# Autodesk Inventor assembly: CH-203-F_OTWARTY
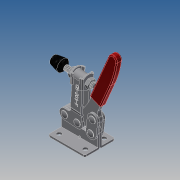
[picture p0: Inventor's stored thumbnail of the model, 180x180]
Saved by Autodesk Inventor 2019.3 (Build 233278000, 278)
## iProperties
Company: Î¢ÈíÖÐ¹ú
Created: 2011-05
Part Number: CH-203-F_OTWARTY
Material: Ogólny
Description: STEP AP203
Document SubType Name: Assembly
Designer: CADENGINEERING4
Sending System: SolidWorks 2010
Preprocessor: SwSTEP 2.0
Title: CH-203-F.STEP
Author: Î¢ÈíÓÃ»§
Revision Number: ÈÎºÎ
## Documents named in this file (10)
- E:\STRONA\Horizontal toggle clamp\CH-203-F\CH-203-F_OTWARTY.iam
- E:\STRONA\Horizontal toggle clamp\CH-203-F\225-D-06.ipt
- E:\STRONA\Horizontal toggle clamp\CH-203-F\203-F-02.ipt
- E:\STRONA\Horizontal toggle clamp\CH-203-F\203-F-04.ipt
- E:\STRONA\Horizontal toggle clamp\CH-203-F\56212-02.ipt
- E:\STRONA\Horizontal toggle clamp\CH-203-F\203-F-03.ipt
- E:\STRONA\Horizontal toggle clamp\CH-203-F\FW516.ipt
- E:\STRONA\Horizontal toggle clamp\CH-203-F\203-F-01.ipt
- E:\STRONA\Horizontal toggle clamp\CH-203-F\203-F-03-02.ipt
- E:\STRONA\Horizontal toggle clamp\CH-203-F\56212.ipt
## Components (15 placed, 15 different names)
1. 225-D-06_1 — Zestawiające:18, Zestawiające:19
2. 225-D-06_2 — Zestawiające:26, Zestawiające:28, Zestawiające:29
3. 203-F-02_3 — Równoległe:1, Zestawiające:5, Zestawiające:7, Zestawiające:9, Zestawiające:25, Zestawiające:26, Zestawiające:27, Zestawiające:29, Zestawiające:30
4. 225-D-06_4 — Zestawiające:20, Zestawiające:22, Zestawiające:23
5. 225-D-06_5 — Zestawiające:13, Zestawiające:30
6. 203-F-04_6 — Zestawiające:14, Zestawiające:16, Zestawiające:18, Zestawiające:19, Zestawiające:21, Zestawiające:22, Zestawiające:23, Zestawiające:24
7. 56212-02_7 — Równoległe:3, Zestawiające:4, Zestawiające:8
8. 203-F-03_8 — Zestawiające:10, Zestawiające:11, Zestawiające:12, Zestawiające:13, Zestawiające:20, Zestawiające:24, Zestawiające:27, Przejściowe:1
9. FW516_9 — Równoległe:2, Zestawiające:1, Zestawiające:5, Zestawiające:6
10. 56212-02_10 — Zestawiające:3, Zestawiające:6
11. 203-F-01_11 — Zestawiające:14, Zestawiające:15, Zestawiające:16, Zestawiające:17, Zestawiające:25, Zestawiające:28, Przejściowe:1
12. 203-F-03-02_12 — Zestawiające:10, Zestawiające:11, Zestawiające:12
13. FW516_13 — Równoległe:1, Równoległe:2, Zestawiające:2, Zestawiające:7, Zestawiające:8
14. 203-F-04_14 — Zestawiające:15, Zestawiające:17, Zestawiające:21
15. 56212_15 — Równoległe:3, Zestawiające:1, Zestawiające:2, Zestawiające:3, Zestawiające:4, Zestawiające:9
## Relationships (34: Mate 30, Flush 3, Transitional 1)
- Równoległe:1 [Flush]: 203-F-02_3 ↔ FW516_13
- Równoległe:2 [Flush]: FW516_9 ↔ FW516_13
- Równoległe:3 [Flush]: 56212-02_7 ↔ 56212_15
- Zestawiające:1 [Mate]: FW516_9 ↔ 56212_15
- Zestawiające:2 [Mate]: FW516_13 ↔ 56212_15
- Zestawiające:3 [Mate]: 56212-02_10 ↔ 56212_15
- Zestawiające:4 [Mate]: 56212-02_7 ↔ 56212_15
- Zestawiające:5 [Mate]: 203-F-02_3 ↔ FW516_9
- Zestawiające:6 [Mate]: FW516_9 ↔ 56212-02_10
- Zestawiające:7 [Mate]: 203-F-02_3 ↔ FW516_13
- Zestawiające:8 [Mate]: 56212-02_7 ↔ FW516_13
- Zestawiające:9 [Mate]: 203-F-02_3 ↔ 56212_15
- Zestawiające:10 [Mate]: 203-F-03_8 ↔ 203-F-03-02_12
- Zestawiające:11 [Mate]: 203-F-03_8 ↔ 203-F-03-02_12
- Zestawiające:12 [Mate]: 203-F-03_8 ↔ 203-F-03-02_12
- Zestawiające:13 [Mate]: 225-D-06_5 ↔ 203-F-03_8
- Zestawiające:14 [Mate]: 203-F-04_6 ↔ 203-F-01_11
- Zestawiające:15 [Mate]: 203-F-01_11 ↔ 203-F-04_14
- Zestawiające:16 [Mate]: 203-F-04_6 ↔ 203-F-01_11
- Zestawiające:17 [Mate]: 203-F-01_11 ↔ 203-F-04_14
- Zestawiające:18 [Mate]: 225-D-06_1 ↔ 203-F-04_6
- Zestawiające:19 [Mate]: 225-D-06_1 ↔ 203-F-04_6
- Zestawiające:20 [Mate]: 225-D-06_4 ↔ 203-F-03_8
- Zestawiające:21 [Mate]: 203-F-04_6 ↔ 203-F-04_14
- Zestawiające:22 [Mate]: 225-D-06_4 ↔ 203-F-04_6
- Zestawiające:23 [Mate]: 225-D-06_4 ↔ 203-F-04_6
- Zestawiające:24 [Mate]: 203-F-04_6 ↔ 203-F-03_8
- Zestawiające:25 [Mate]: 203-F-02_3 ↔ 203-F-01_11
- Zestawiające:26 [Mate]: 225-D-06_2 ↔ 203-F-02_3
- Zestawiające:27 [Mate]: 203-F-02_3 ↔ 203-F-03_8
- Zestawiające:28 [Mate]: 225-D-06_2 ↔ 203-F-01_11
- Zestawiające:29 [Mate]: 225-D-06_2 ↔ 203-F-02_3
- Zestawiające:30 [Mate]: 203-F-02_3 ↔ 225-D-06_5
- Przejściowe:1 [Transitional]: 203-F-03_8 ↔ 203-F-01_11
